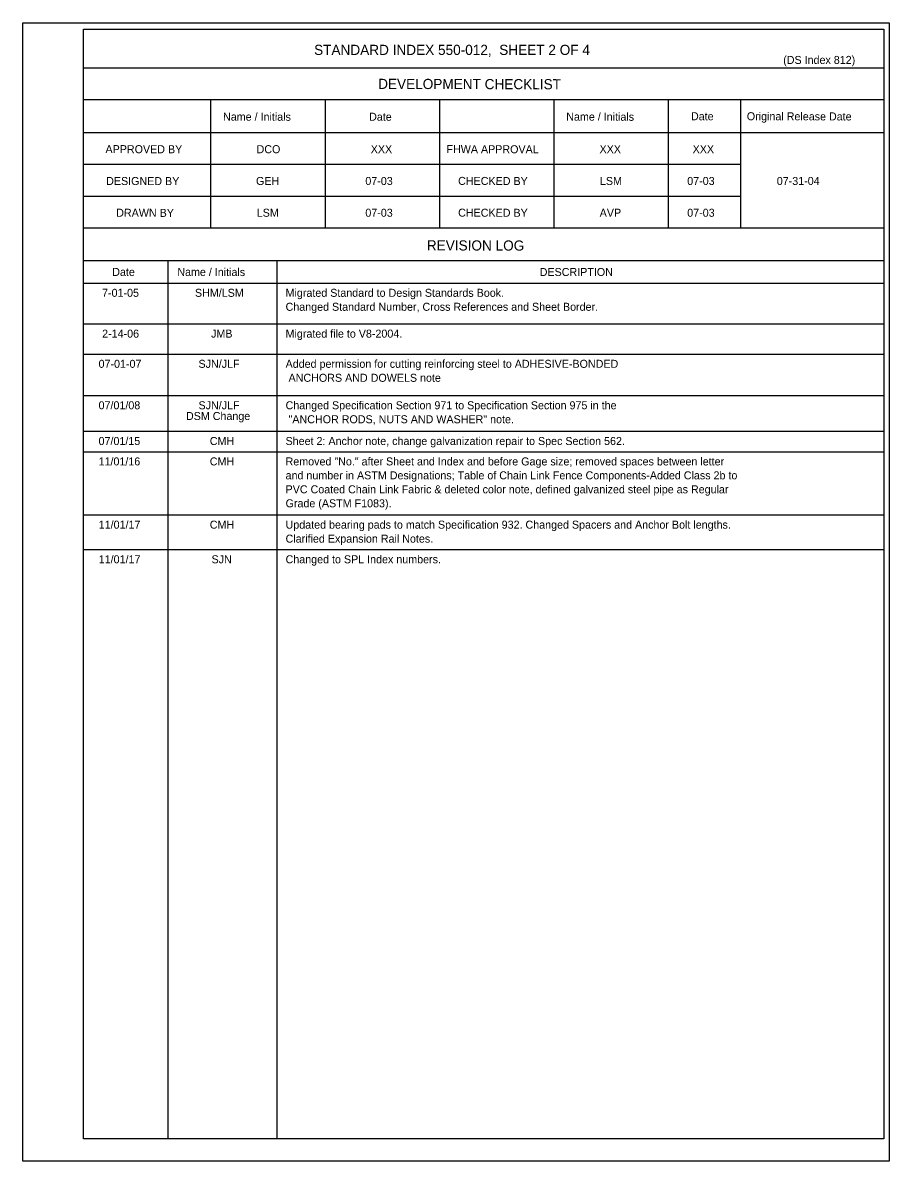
# Model space of a CAD drawing. Extents: x 110393.5 to 110429.5, y 110427.9 to 110443.1.
# Drawn here: x 110418.62 to 110429.53, y 110427.89 to 110442.23 of the extents above; entities that cross this region are included whole.
import ezdxf

# ---------------------------------------------------------------- set-up
doc = ezdxf.new("R2010")
doc.units = 0
for name, color, linetype in [('AdhocPoint_dp', 7, 'Continuous'), ('Border', 7, 'Continuous'), ('SheetBorder_dp', 7, 'Continuous')]:
    doc.layers.add(name, color=color, linetype=linetype)

msp = doc.modelspace()

# ---------------------------------------------------------------- linework, layer by layer
at = {"layer": 'Border'}
for p, q in [((110429.461, 110441.657), (110419.388, 110441.657)), ((110429.461, 110441.257), (110419.388, 110441.257)), ((110420.988, 110441.257), (110420.988, 110439.643)), ((110422.428, 110441.257), (110422.428, 110439.643)), ((110423.868, 110441.257), (110423.868, 110439.643)), ((110425.308, 110441.257), (110425.308, 110439.643)), ((110426.748, 110441.257), (110426.748, 110439.643)), ((110427.656, 110441.257), (110427.656, 110439.643)), ((110429.461, 110440.843), (110419.388, 110440.843)), ((110427.656, 110440.443), (110419.388, 110440.443)), ((110427.656, 110440.043), (110419.388, 110440.043)), ((110429.461, 110439.643), (110419.388, 110439.643)), ((110429.461, 110439.229), (110419.388, 110439.229)), ((110420.448, 110439.229), (110420.448, 110428.176)), ((110421.819, 110439.229), (110421.819, 110428.176)), ((110429.461, 110438.947), (110419.388, 110438.947)), ((110429.461, 110438.433), (110419.388, 110438.433)), ((110429.461, 110438.053), (110419.388, 110438.053)), ((110429.461, 110437.531), (110419.388, 110437.531)), ((110429.461, 110437.081), (110419.388, 110437.081)), ((110429.461, 110436.824), (110419.388, 110436.824)), ((110429.461, 110436.028), (110419.388, 110436.028)), ((110429.461, 110435.592), (110419.388, 110435.592))]:
    msp.add_line(p, q, dxfattribs=at)
msp.add_lwpolyline([(110419.388, 110442.147), (110429.461, 110442.147), (110429.461, 110428.176), (110419.388, 110428.176)], close=True, dxfattribs=at)
at = {"layer": 'SheetBorder_dp'}
msp.add_line((110418.623, 110427.895), (110418.623, 110427.895), dxfattribs=at)
msp.add_lwpolyline([(110418.623, 110442.228), (110429.53, 110442.228), (110429.53, 110427.895), (110418.623, 110427.895)], close=True, dxfattribs=at)

# ---------------------------------------------------------------- texts
at = {"layer": 'AdhocPoint_dp'}
for s, height, p in [('STANDARD INDEX 550-012,  SHEET 2 OF 4', 0.128, (110422.29, 110441.823)), ('(DS Index 812)', 0.1008, (110428.195, 110441.71)), ('DCO', 0.1008, (110421.566, 110440.586)), ('XXX', 0.1008, (110423.003, 110440.586)), ('XXX', 0.1008, (110425.883, 110440.586)), ('XXX', 0.1008, (110427.055, 110440.586)), ('GEH', 0.1008, (110421.559, 110440.186)), ('07-03', 0.1008, (110422.935, 110440.186)), ('LSM', 0.1008, (110425.888, 110440.186)), ('07-03', 0.1008, (110426.987, 110440.186)), ('07-31-04', 0.1008, (110428.114, 110440.186)), ('LSM', 0.1008, (110421.568, 110439.786)), ('07-03', 0.1008, (110422.935, 110439.786)), ('AVP', 0.1008, (110425.885, 110439.786)), ('07-03', 0.1008, (110426.987, 110439.786)), ('DESCRIPTION', 0.1008, (110425.13, 110439.04)), ('7-01-05', 0.1008, (110419.621, 110438.778)), ('SHM/LSM', 0.1008, (110420.79, 110438.778)), ('Migrated Standard to Design Standards Book.', 0.1008, (110421.931, 110438.778)), ('Changed Standard Number, Cross References and Sheet Border.', 0.1008, (110421.931, 110438.602)), ('2-14-06', 0.1008, (110419.622, 110438.264)), ('JMB', 0.1008, (110420.993, 110438.264)), ('Migrated file to V8-2004.', 0.1008, (110421.931, 110438.264)), ('07-01-07', 0.1008, (110419.577, 110437.884)), ('SJN/JLF', 0.1008, (110420.835, 110437.884)), ('Added permission for cutting reinforcing steel to ADHESIVE-BONDED ', 0.1008, (110421.931, 110437.884)), (' ANCHORS AND DOWELS note', 0.1008, (110421.931, 110437.708)), ('07/01/08', 0.1008, (110419.577, 110437.362)), ('SJN/JLF', 0.1008, (110420.835, 110437.362)), ('Changed Specification Section 971 to Specification Section 975 in the ', 0.1008, (110421.931, 110437.362)), ('DSM Change', 0.1008, (110420.677, 110437.227)), (' "ANCHOR RODS, NUTS AND WASHER" note.', 0.1008, (110421.931, 110437.186)), ('07/01/15', 0.1008, (110419.577, 110436.912)), ('CMH', 0.1008, (110420.977, 110436.912)), ('Sheet 2: Anchor note, change galvanization repair to Spec Section 562.', 0.1008, (110421.931, 110436.912)), ('11/01/16', 0.1008, (110419.577, 110436.655)), ('CMH', 0.1008, (110420.977, 110436.655)), ('Removed "No." after Sheet and Index and before Gage size; removed spaces between letter', 0.1008, (110421.931, 110436.655)), ('and number in ASTM Designations; Table of Chain Link Fence Components-Added Class 2b to', 0.1008, (110421.931, 110436.48)), ('PVC Coated Chain Link Fabric & deleted color note, defined galvanized steel pipe as Regular', 0.1008, (110421.931, 110436.304)), ('Grade (ASTM F1083).', 0.1008, (110421.931, 110436.128)), ('11/01/17', 0.1008, (110419.579, 110435.859)), ('Updated bearing pads to match Specification 932. Changed Spacers and Anchor Bolt lengths.', 0.1008, (110421.931, 110435.859)), ('CMH', 0.1008, (110420.977, 110435.859)), ('Clarified Expansion Rail Notes.', 0.1008, (110421.931, 110435.683)), ('11/01/17', 0.1008, (110419.579, 110435.423)), ('SJN', 0.1008, (110420.999, 110435.423)), ('Changed to SPL Index numbers.', 0.1008, (110421.931, 110435.423))]:
    msp.add_text(s, height=height, dxfattribs=at).set_placement(p)
for s, height, p in [('DEVELOPMENT CHECKLIST', 0.128, (110423.096, 110441.395)), ('Name / Initials', 0.1008, (110421.144, 110440.996)), ('Date', 0.1008, (110422.982, 110440.995)), ('Name / Initials', 0.1008, (110425.464, 110440.996)), ('Date', 0.1008, (110427.034, 110441.001)), ('Original Release Date', 0.1008, (110427.737, 110441.001)), ('APPROVED BY', 0.1008, (110419.664, 110440.587)), ('FHWA APPROVAL', 0.1008, (110423.956, 110440.587)), ('DESIGNED BY', 0.1008, (110419.672, 110440.186)), ('CHECKED BY', 0.1008, (110424.103, 110440.187)), ('DRAWN BY', 0.1008, (110419.799, 110439.786)), ('CHECKED BY', 0.1008, (110424.103, 110439.787)), ('REVISION LOG', 0.128, (110423.709, 110439.362)), ('Date', 0.1008, (110419.749, 110439.041)), ('Name / Initials', 0.1008, (110420.568, 110439.041))]:
    msp.add_text(s, height=height, rotation=359.8756, dxfattribs=at).set_placement(p)

doc.saveas('drawing.dxf')
